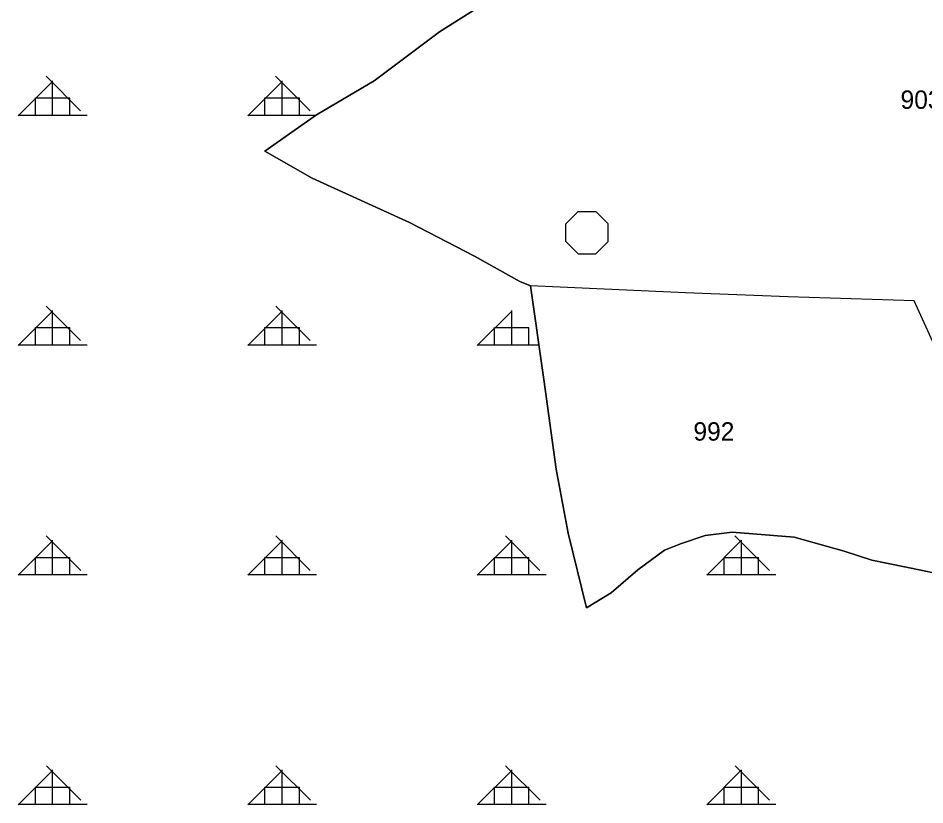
# Model space of a CAD drawing. Extents: x 410727 to 412947, y 4463506 to 4466382.
# Drawn here: x 411997.1 to 412194.6, y 4465173 to 4465344.2 of the extents above; entities that cross this region are included whole.
import ezdxf

# ---------------------------------------------------------------- set-up
doc = ezdxf.new("R2010")
doc.units = 0
for name, color, linetype in [('ADAKENARI', 7, 'Continuous'), ('KDS_PARSEL_NO', 7, 'Continuous'), ('KDS_PL', 7, 'Continuous'), ('PL_AYA_ORMAN', 7, 'Continuous'), ('PL_KA_TARIM_DIGER', 7, 'Continuous'), ('TR_ORMAN', 7, 'Continuous'), ('TR_TARIMALANI', 7, 'Continuous')]:
    doc.layers.add(name, color=color, linetype=linetype)

msp = doc.modelspace()

# ---------------------------------------------------------------- linework, layer by layer
at = {"layer": 'ADAKENARI'}
for p, q in [((412098.34, 4465347.2), (412088.91, 4465341.23)), ((412088.91, 4465341.23), (412074.64, 4465330.54)), ((412074.64, 4465330.54), (412062.11, 4465323.2)), ((412062.11, 4465323.2), (412050.82, 4465315.25)), ((412050.82, 4465315.25), (412061.12, 4465309.4)), ((412061.12, 4465309.4), (412082.33, 4465299.71)), ((412082.33, 4465299.71), (412096.48, 4465292.37)), ((412096.48, 4465292.37), (412106.4, 4465286.9)), ((412106.4, 4465286.9), (412108.68, 4465285.94)), ((412108.68, 4465285.94), (412111.63, 4465265.58)), ((412111.63, 4465265.58), (412114.28, 4465246.01)), ((412114.28, 4465246.01), (412116.93, 4465232.08)), ((412146.76, 4465231.62), (412152.64, 4465232.35)), ((412152.64, 4465232.35), (412166.15, 4465231.22)), ((412116.93, 4465232.08), (412120.9, 4465215.82)), ((412141.61, 4465229.85), (412146.76, 4465231.62)), ((412166.15, 4465231.22), (412177.01, 4465228.16)), ((412132.04, 4465224.13), (412137.91, 4465228.4)), ((412137.91, 4465228.4), (412141.61, 4465229.85)), ((412177.01, 4465228.16), (412183.05, 4465226.22)), ((412183.05, 4465226.22), (412194.07, 4465223.96)), ((412126.25, 4465219.13), (412132.04, 4465224.13)), ((412194.07, 4465223.96), (412202.76, 4465222.11)), ((412120.9, 4465215.82), (412126.25, 4465219.13))]:
    msp.add_line(p, q, dxfattribs=at)
at = {"layer": 'KDS_PL'}
for p, q in [((412088.91, 4465341.23), (412098.34, 4465347.2)), ((412074.64, 4465330.54), (412088.91, 4465341.23)), ((412062.11, 4465323.2), (412074.64, 4465330.54)), ((412050.82, 4465315.25), (412062.11, 4465323.2)), ((412061.12, 4465309.4), (412050.82, 4465315.25)), ((412082.33, 4465299.71), (412061.12, 4465309.4)), ((412096.48, 4465292.37), (412082.33, 4465299.71)), ((412106.4, 4465286.9), (412096.48, 4465292.37)), ((412108.68, 4465285.94), (412106.4, 4465286.9)), ((412142.42, 4465284.44), (412108.68, 4465285.94)), ((412108.68, 4465285.94), (412111.63, 4465265.58)), ((412164.81, 4465283.54), (412142.42, 4465284.44)), ((412192.28, 4465282.65), (412164.81, 4465283.54)), ((412197.06, 4465272.17), (412192.28, 4465282.65)), ((412111.63, 4465265.58), (412114.28, 4465246.01)), ((412114.28, 4465246.01), (412116.93, 4465232.08)), ((412146.76, 4465231.62), (412152.64, 4465232.35)), ((412152.64, 4465232.35), (412166.15, 4465231.22)), ((412116.93, 4465232.08), (412120.9, 4465215.82)), ((412141.61, 4465229.85), (412146.76, 4465231.62)), ((412166.15, 4465231.22), (412177.01, 4465228.16)), ((412132.04, 4465224.13), (412137.91, 4465228.4)), ((412137.91, 4465228.4), (412141.61, 4465229.85)), ((412177.01, 4465228.16), (412183.05, 4465226.22)), ((412183.05, 4465226.22), (412194.07, 4465223.96)), ((412126.25, 4465219.13), (412132.04, 4465224.13)), ((412194.07, 4465223.96), (412202.76, 4465222.11)), ((412120.9, 4465215.82), (412126.25, 4465219.13))]:
    msp.add_line(p, q, dxfattribs=at)
at = {"layer": 'PL_AYA_ORMAN'}
msp.add_lwpolyline([(412202.76, 4465222.11), (412194.07, 4465223.96), (412183.05, 4465226.22), (412177.01, 4465228.16), (412166.15, 4465231.22), (412152.64, 4465232.35), (412146.76, 4465231.62), (412141.61, 4465229.85), (412137.91, 4465228.4), (412132.04, 4465224.13), (412126.25, 4465219.13), (412120.9, 4465215.82), (412116.93, 4465232.08), (412114.28, 4465246.01), (412111.63, 4465265.58), (412108.68, 4465285.94), (412106.4, 4465286.9), (412096.48, 4465292.37), (412082.33, 4465299.71), (412061.12, 4465309.4), (412050.82, 4465315.25), (412062.11, 4465323.2), (412074.64, 4465330.54), (412088.91, 4465341.23), (412098.34, 4465347.2)], dxfattribs=at)
at = {"layer": 'PL_KA_TARIM_DIGER'}
msp.add_lwpolyline([(412202.76, 4465222.11), (412194.07, 4465223.96), (412183.05, 4465226.22), (412177.01, 4465228.16), (412166.15, 4465231.22), (412152.64, 4465232.35), (412146.76, 4465231.62), (412141.61, 4465229.85), (412137.91, 4465228.4), (412132.04, 4465224.13), (412126.25, 4465219.13), (412120.9, 4465215.82), (412116.93, 4465232.08), (412114.28, 4465246.01), (412111.63, 4465265.58), (412108.68, 4465285.94), (412106.4, 4465286.9), (412096.48, 4465292.37), (412082.33, 4465299.71), (412061.12, 4465309.4), (412050.82, 4465315.25), (412062.11, 4465323.2), (412074.64, 4465330.54), (412088.91, 4465341.23), (412098.34, 4465347.2)], dxfattribs=at)
at = {"layer": 'TR_ORMAN'}
for p, q in [((412010.69, 4465324.06), (412003.19, 4465331.56)), ((412010.69, 4465324.06), (412003.19, 4465331.56)), ((412010.69, 4465324.06), (412003.19, 4465331.56)), ((412010.69, 4465324.06), (412003.19, 4465331.56)), ((412060.68, 4465324.06), (412053.18, 4465331.56)), ((412060.68, 4465324.06), (412053.18, 4465331.56)), ((412060.68, 4465324.06), (412053.18, 4465331.56)), ((412060.68, 4465324.06), (412053.18, 4465331.56)), ((412060.68, 4465324.06), (412053.18, 4465331.56)), ((412060.68, 4465324.06), (412053.18, 4465331.56)), ((412060.68, 4465324.06), (412053.18, 4465331.56)), ((412060.68, 4465324.06), (412053.18, 4465331.56)), ((411997.11, 4465322.94), (412004.61, 4465330.44)), ((411997.11, 4465322.94), (412004.61, 4465330.44)), ((411997.11, 4465322.94), (412004.61, 4465330.44)), ((411997.11, 4465322.94), (412004.61, 4465330.44)), ((412004.62, 4465323.09), (412004.62, 4465330.59)), ((412004.62, 4465323.09), (412004.62, 4465330.59)), ((412004.62, 4465323.09), (412004.62, 4465330.59)), ((412004.62, 4465323.09), (412004.62, 4465330.59)), ((412047.11, 4465322.95), (412054.61, 4465330.45)), ((412047.11, 4465322.95), (412054.61, 4465330.45)), ((412047.11, 4465322.95), (412054.61, 4465330.45)), ((412047.11, 4465322.95), (412054.61, 4465330.45)), ((412054.62, 4465323.09), (412054.62, 4465330.59)), ((412054.62, 4465323.09), (412054.62, 4465330.59)), ((412054.62, 4465323.09), (412054.62, 4465330.59)), ((412054.62, 4465323.09), (412054.62, 4465330.59)), ((412000.87, 4465323.09), (412000.87, 4465326.84)), ((412000.87, 4465326.84), (412008.37, 4465326.84)), ((412000.87, 4465323.09), (412000.87, 4465326.84)), ((412000.87, 4465326.84), (412008.37, 4465326.84)), ((412000.87, 4465323.09), (412000.87, 4465326.84)), ((412000.87, 4465326.84), (412008.37, 4465326.84)), ((412000.87, 4465323.09), (412000.87, 4465326.84)), ((412000.87, 4465326.84), (412008.37, 4465326.84)), ((412008.37, 4465323.09), (412008.37, 4465326.84)), ((412008.37, 4465323.09), (412008.37, 4465326.84)), ((412008.37, 4465323.09), (412008.37, 4465326.84)), ((412008.37, 4465323.09), (412008.37, 4465326.84)), ((412050.87, 4465323.09), (412050.87, 4465326.84)), ((412050.87, 4465326.84), (412058.37, 4465326.84)), ((412050.87, 4465323.09), (412050.87, 4465326.84)), ((412050.87, 4465326.84), (412058.37, 4465326.84)), ((412050.87, 4465323.09), (412050.87, 4465326.84)), ((412050.87, 4465326.84), (412058.37, 4465326.84)), ((412050.87, 4465323.09), (412050.87, 4465326.84)), ((412050.87, 4465326.84), (412058.37, 4465326.84)), ((412058.37, 4465323.09), (412058.37, 4465326.84)), ((412058.37, 4465323.09), (412058.37, 4465326.84)), ((412058.37, 4465323.09), (412058.37, 4465326.84)), ((412058.37, 4465323.09), (412058.37, 4465326.84)), ((411997.12, 4465323.09), (412012.12, 4465323.09)), ((411997.12, 4465323.09), (412012.12, 4465323.09)), ((411997.12, 4465323.09), (412012.12, 4465323.09)), ((411997.12, 4465323.09), (412012.12, 4465323.09)), ((412047.12, 4465323.09), (412061.95, 4465323.09)), ((412047.12, 4465323.09), (412061.95, 4465323.09)), ((412047.12, 4465323.09), (412061.95, 4465323.09)), ((412047.12, 4465323.09), (412061.95, 4465323.09)), ((412010.72, 4465274.04), (412003.22, 4465281.54)), ((412010.72, 4465274.04), (412003.22, 4465281.54)), ((412010.72, 4465274.04), (412003.22, 4465281.54)), ((412010.72, 4465274.04), (412003.22, 4465281.54)), ((412060.71, 4465274.04), (412053.21, 4465281.54)), ((412060.71, 4465274.04), (412053.21, 4465281.54)), ((412060.71, 4465274.04), (412053.21, 4465281.54)), ((412060.71, 4465274.04), (412053.21, 4465281.54)), ((411997.11, 4465272.95), (412004.61, 4465280.45)), ((411997.11, 4465272.95), (412004.61, 4465280.45)), ((411997.11, 4465272.95), (412004.61, 4465280.45)), ((411997.11, 4465272.95), (412004.61, 4465280.45)), ((412004.62, 4465273.09), (412004.62, 4465280.59)), ((412004.62, 4465273.09), (412004.62, 4465280.59)), ((412004.62, 4465273.09), (412004.62, 4465280.59)), ((412004.62, 4465273.09), (412004.62, 4465280.59)), ((412047.11, 4465272.96), (412054.61, 4465280.46)), ((412047.11, 4465272.96), (412054.61, 4465280.46)), ((412047.11, 4465272.96), (412054.61, 4465280.46)), ((412047.11, 4465272.96), (412054.61, 4465280.46)), ((412054.62, 4465273.09), (412054.62, 4465280.59)), ((412054.62, 4465273.09), (412054.62, 4465280.59)), ((412054.62, 4465273.09), (412054.62, 4465280.59)), ((412054.62, 4465273.09), (412054.62, 4465280.59)), ((412097.11, 4465272.97), (412104.61, 4465280.46)), ((412097.11, 4465272.97), (412104.61, 4465280.46)), ((412097.11, 4465272.97), (412104.61, 4465280.46)), ((412097.11, 4465272.97), (412104.61, 4465280.46)), ((412104.62, 4465273.09), (412104.62, 4465280.59)), ((412104.62, 4465273.09), (412104.62, 4465280.59)), ((412104.62, 4465273.09), (412104.62, 4465280.59)), ((412104.62, 4465273.09), (412104.62, 4465280.59)), ((412000.87, 4465273.09), (412000.87, 4465276.84)), ((412000.87, 4465276.84), (412008.37, 4465276.84)), ((412000.87, 4465273.09), (412000.87, 4465276.84)), ((412000.87, 4465276.84), (412008.37, 4465276.84)), ((412000.87, 4465273.09), (412000.87, 4465276.84)), ((412000.87, 4465276.84), (412008.37, 4465276.84)), ((412000.87, 4465273.09), (412000.87, 4465276.84)), ((412000.87, 4465276.84), (412008.37, 4465276.84)), ((412008.37, 4465273.09), (412008.37, 4465276.84)), ((412008.37, 4465273.09), (412008.37, 4465276.84)), ((412008.37, 4465273.09), (412008.37, 4465276.84)), ((412008.37, 4465273.09), (412008.37, 4465276.84)), ((412050.87, 4465273.09), (412050.87, 4465276.84)), ((412050.87, 4465276.84), (412058.37, 4465276.84)), ((412050.87, 4465273.09), (412050.87, 4465276.84)), ((412050.87, 4465276.84), (412058.37, 4465276.84)), ((412050.87, 4465273.09), (412050.87, 4465276.84)), ((412050.87, 4465276.84), (412058.37, 4465276.84)), ((412050.87, 4465273.09), (412050.87, 4465276.84)), ((412050.87, 4465276.84), (412058.37, 4465276.84)), ((412058.37, 4465273.09), (412058.37, 4465276.84)), ((412058.37, 4465273.09), (412058.37, 4465276.84)), ((412058.37, 4465273.09), (412058.37, 4465276.84)), ((412058.37, 4465273.09), (412058.37, 4465276.84)), ((412100.87, 4465273.09), (412100.87, 4465276.84)), ((412100.87, 4465276.84), (412108.37, 4465276.84)), ((412100.87, 4465273.09), (412100.87, 4465276.84)), ((412100.87, 4465276.84), (412108.37, 4465276.84)), ((412100.87, 4465273.09), (412100.87, 4465276.84)), ((412100.87, 4465276.84), (412108.37, 4465276.84)), ((412100.87, 4465273.09), (412100.87, 4465276.84)), ((412100.87, 4465276.84), (412108.37, 4465276.84)), ((412108.37, 4465273.09), (412108.37, 4465276.84)), ((412108.37, 4465273.09), (412108.37, 4465276.84)), ((412108.37, 4465273.09), (412108.37, 4465276.84)), ((412108.37, 4465273.09), (412108.37, 4465276.84)), ((411997.12, 4465273.09), (412012.12, 4465273.09)), ((411997.12, 4465273.09), (412012.12, 4465273.09)), ((411997.12, 4465273.09), (412012.12, 4465273.09)), ((411997.12, 4465273.09), (412012.12, 4465273.09)), ((412047.12, 4465273.09), (412062.12, 4465273.09)), ((412047.12, 4465273.09), (412062.12, 4465273.09)), ((412047.12, 4465273.09), (412062.12, 4465273.09)), ((412047.12, 4465273.09), (412062.12, 4465273.09)), ((412097.12, 4465273.09), (412110.54, 4465273.09)), ((412097.12, 4465273.09), (412110.54, 4465273.09)), ((412097.12, 4465273.09), (412110.54, 4465273.09)), ((412097.12, 4465273.09), (412110.54, 4465273.09)), ((411997.11, 4465222.96), (412004.61, 4465230.46)), ((411997.11, 4465222.96), (412004.61, 4465230.46)), ((411997.11, 4465222.96), (412004.61, 4465230.46)), ((411997.11, 4465222.96), (412004.61, 4465230.46)), ((412010.75, 4465224.01), (412003.25, 4465231.51)), ((412010.75, 4465224.01), (412003.25, 4465231.51)), ((412010.75, 4465224.01), (412003.25, 4465231.51)), ((412010.75, 4465224.01), (412003.25, 4465231.51)), ((412004.62, 4465223.09), (412004.62, 4465230.59)), ((412004.62, 4465223.09), (412004.62, 4465230.59)), ((412004.62, 4465223.09), (412004.62, 4465230.59)), ((412004.62, 4465223.09), (412004.62, 4465230.59)), ((412047.11, 4465222.97), (412054.61, 4465230.46)), ((412047.11, 4465222.97), (412054.61, 4465230.46)), ((412047.11, 4465222.97), (412054.61, 4465230.46)), ((412047.11, 4465222.97), (412054.61, 4465230.46)), ((412060.74, 4465224.01), (412053.24, 4465231.51)), ((412060.74, 4465224.01), (412053.24, 4465231.51)), ((412060.74, 4465224.01), (412053.24, 4465231.51)), ((412060.74, 4465224.01), (412053.24, 4465231.51)), ((412054.62, 4465223.09), (412054.62, 4465230.59)), ((412054.62, 4465223.09), (412054.62, 4465230.59)), ((412054.62, 4465223.09), (412054.62, 4465230.59)), ((412054.62, 4465223.09), (412054.62, 4465230.59)), ((412097.11, 4465222.97), (412104.61, 4465230.47)), ((412097.11, 4465222.97), (412104.61, 4465230.47)), ((412097.11, 4465222.97), (412104.61, 4465230.47)), ((412097.11, 4465222.97), (412104.61, 4465230.47)), ((412110.73, 4465224.01), (412103.23, 4465231.51)), ((412110.73, 4465224.01), (412103.23, 4465231.51)), ((412110.73, 4465224.01), (412103.23, 4465231.51)), ((412110.73, 4465224.01), (412103.23, 4465231.51)), ((412104.62, 4465223.09), (412104.62, 4465230.59)), ((412104.62, 4465223.09), (412104.62, 4465230.59)), ((412104.62, 4465223.09), (412104.62, 4465230.59)), ((412104.62, 4465223.09), (412104.62, 4465230.59)), ((412147.11, 4465222.98), (412154.61, 4465230.48)), ((412147.11, 4465222.98), (412154.61, 4465230.48)), ((412147.11, 4465222.98), (412154.61, 4465230.48)), ((412147.11, 4465222.98), (412154.61, 4465230.48)), ((412160.73, 4465224.01), (412153.23, 4465231.51)), ((412160.73, 4465224.01), (412153.23, 4465231.51)), ((412160.73, 4465224.01), (412153.23, 4465231.51)), ((412160.73, 4465224.01), (412153.23, 4465231.51)), ((412154.62, 4465223.09), (412154.62, 4465230.59)), ((412154.62, 4465223.09), (412154.62, 4465230.59)), ((412154.62, 4465223.09), (412154.62, 4465230.59)), ((412154.62, 4465223.09), (412154.62, 4465230.59)), ((412000.87, 4465223.09), (412000.87, 4465226.84)), ((412000.87, 4465226.84), (412008.37, 4465226.84)), ((412000.87, 4465223.09), (412000.87, 4465226.84)), ((412000.87, 4465226.84), (412008.37, 4465226.84)), ((412000.87, 4465223.09), (412000.87, 4465226.84)), ((412000.87, 4465226.84), (412008.37, 4465226.84)), ((412000.87, 4465223.09), (412000.87, 4465226.84)), ((412000.87, 4465226.84), (412008.37, 4465226.84)), ((412008.37, 4465223.09), (412008.37, 4465226.84)), ((412008.37, 4465223.09), (412008.37, 4465226.84)), ((412008.37, 4465223.09), (412008.37, 4465226.84)), ((412008.37, 4465223.09), (412008.37, 4465226.84)), ((412050.87, 4465223.09), (412050.87, 4465226.84)), ((412050.87, 4465226.84), (412058.37, 4465226.84)), ((412050.87, 4465223.09), (412050.87, 4465226.84)), ((412050.87, 4465226.84), (412058.37, 4465226.84)), ((412050.87, 4465223.09), (412050.87, 4465226.84)), ((412050.87, 4465226.84), (412058.37, 4465226.84)), ((412050.87, 4465223.09), (412050.87, 4465226.84)), ((412050.87, 4465226.84), (412058.37, 4465226.84)), ((412058.37, 4465223.09), (412058.37, 4465226.84)), ((412058.37, 4465223.09), (412058.37, 4465226.84)), ((412058.37, 4465223.09), (412058.37, 4465226.84)), ((412058.37, 4465223.09), (412058.37, 4465226.84)), ((412100.87, 4465223.09), (412100.87, 4465226.84)), ((412100.87, 4465226.84), (412108.37, 4465226.84)), ((412100.87, 4465223.09), (412100.87, 4465226.84)), ((412100.87, 4465226.84), (412108.37, 4465226.84)), ((412100.87, 4465223.09), (412100.87, 4465226.84)), ((412100.87, 4465226.84), (412108.37, 4465226.84)), ((412100.87, 4465223.09), (412100.87, 4465226.84)), ((412100.87, 4465226.84), (412108.37, 4465226.84)), ((412108.37, 4465223.09), (412108.37, 4465226.84)), ((412108.37, 4465223.09), (412108.37, 4465226.84)), ((412108.37, 4465223.09), (412108.37, 4465226.84)), ((412108.37, 4465223.09), (412108.37, 4465226.84)), ((412150.87, 4465223.09), (412150.87, 4465226.84)), ((412150.87, 4465226.84), (412158.37, 4465226.84)), ((412150.87, 4465223.09), (412150.87, 4465226.84)), ((412150.87, 4465226.84), (412158.37, 4465226.84)), ((412150.87, 4465223.09), (412150.87, 4465226.84)), ((412150.87, 4465226.84), (412158.37, 4465226.84)), ((412150.87, 4465223.09), (412150.87, 4465226.84)), ((412150.87, 4465226.84), (412158.37, 4465226.84)), ((412158.37, 4465223.09), (412158.37, 4465226.84)), ((412158.37, 4465223.09), (412158.37, 4465226.84)), ((412158.37, 4465223.09), (412158.37, 4465226.84)), ((412158.37, 4465223.09), (412158.37, 4465226.84)), ((411997.12, 4465223.09), (412012.12, 4465223.09)), ((411997.12, 4465223.09), (412012.12, 4465223.09)), ((411997.12, 4465223.09), (412012.12, 4465223.09)), ((411997.12, 4465223.09), (412012.12, 4465223.09)), ((412047.12, 4465223.09), (412062.12, 4465223.09)), ((412047.12, 4465223.09), (412062.12, 4465223.09)), ((412047.12, 4465223.09), (412062.12, 4465223.09)), ((412047.12, 4465223.09), (412062.12, 4465223.09)), ((412097.12, 4465223.09), (412112.12, 4465223.09)), ((412097.12, 4465223.09), (412112.12, 4465223.09)), ((412097.12, 4465223.09), (412112.12, 4465223.09)), ((412097.12, 4465223.09), (412112.12, 4465223.09)), ((412147.12, 4465223.09), (412162.12, 4465223.09)), ((412147.12, 4465223.09), (412162.12, 4465223.09)), ((412147.12, 4465223.09), (412162.12, 4465223.09)), ((412147.12, 4465223.09), (412162.12, 4465223.09)), ((412010.78, 4465173.99), (412003.28, 4465181.49)), ((412010.78, 4465173.99), (412003.28, 4465181.49)), ((412010.78, 4465173.99), (412003.28, 4465181.49)), ((412010.78, 4465173.99), (412003.28, 4465181.49)), ((412060.77, 4465173.99), (412053.27, 4465181.49)), ((412060.77, 4465173.99), (412053.27, 4465181.49)), ((412060.77, 4465173.99), (412053.27, 4465181.49)), ((412060.77, 4465173.99), (412053.27, 4465181.49)), ((412110.77, 4465173.99), (412103.27, 4465181.49)), ((412110.77, 4465173.99), (412103.27, 4465181.49)), ((412110.77, 4465173.99), (412103.27, 4465181.49)), ((412110.77, 4465173.99), (412103.27, 4465181.49)), ((412160.76, 4465173.99), (412153.26, 4465181.49)), ((412160.76, 4465173.99), (412153.26, 4465181.49)), ((412160.76, 4465173.99), (412153.26, 4465181.49)), ((412160.76, 4465173.99), (412153.26, 4465181.49)), ((411997.11, 4465172.97), (412004.61, 4465180.47)), ((411997.11, 4465172.97), (412004.61, 4465180.47)), ((411997.11, 4465172.97), (412004.61, 4465180.47)), ((411997.11, 4465172.97), (412004.61, 4465180.47)), ((412004.62, 4465173.09), (412004.62, 4465180.59)), ((412004.62, 4465173.09), (412004.62, 4465180.59)), ((412004.62, 4465173.09), (412004.62, 4465180.59)), ((412004.62, 4465173.09), (412004.62, 4465180.59)), ((412047.11, 4465172.97), (412054.61, 4465180.47)), ((412047.11, 4465172.97), (412054.61, 4465180.47)), ((412047.11, 4465172.97), (412054.61, 4465180.47)), ((412047.11, 4465172.97), (412054.61, 4465180.47)), ((412054.62, 4465173.09), (412054.62, 4465180.59)), ((412054.62, 4465173.09), (412054.62, 4465180.59)), ((412054.62, 4465173.09), (412054.62, 4465180.59)), ((412054.62, 4465173.09), (412054.62, 4465180.59)), ((412097.11, 4465172.98), (412104.61, 4465180.48)), ((412097.11, 4465172.98), (412104.61, 4465180.48)), ((412097.11, 4465172.98), (412104.61, 4465180.48)), ((412097.11, 4465172.98), (412104.61, 4465180.48)), ((412104.62, 4465173.09), (412104.62, 4465180.59)), ((412104.62, 4465173.09), (412104.62, 4465180.59)), ((412104.62, 4465173.09), (412104.62, 4465180.59)), ((412104.62, 4465173.09), (412104.62, 4465180.59)), ((412147.11, 4465172.99), (412154.61, 4465180.49)), ((412147.11, 4465172.99), (412154.61, 4465180.49)), ((412147.11, 4465172.99), (412154.61, 4465180.49)), ((412147.11, 4465172.99), (412154.61, 4465180.49)), ((412154.62, 4465173.09), (412154.62, 4465180.59)), ((412154.62, 4465173.09), (412154.62, 4465180.59)), ((412154.62, 4465173.09), (412154.62, 4465180.59)), ((412154.62, 4465173.09), (412154.62, 4465180.59)), ((412000.87, 4465173.09), (412000.87, 4465176.84)), ((412000.87, 4465176.84), (412008.37, 4465176.84)), ((412000.87, 4465173.09), (412000.87, 4465176.84)), ((412000.87, 4465176.84), (412008.37, 4465176.84)), ((412000.87, 4465173.09), (412000.87, 4465176.84)), ((412000.87, 4465176.84), (412008.37, 4465176.84)), ((412000.87, 4465173.09), (412000.87, 4465176.84)), ((412000.87, 4465176.84), (412008.37, 4465176.84)), ((412008.37, 4465173.09), (412008.37, 4465176.84)), ((412008.37, 4465173.09), (412008.37, 4465176.84)), ((412008.37, 4465173.09), (412008.37, 4465176.84)), ((412008.37, 4465173.09), (412008.37, 4465176.84)), ((412050.87, 4465173.09), (412050.87, 4465176.84)), ((412050.87, 4465176.84), (412058.37, 4465176.84)), ((412050.87, 4465173.09), (412050.87, 4465176.84)), ((412050.87, 4465176.84), (412058.37, 4465176.84)), ((412050.87, 4465173.09), (412050.87, 4465176.84)), ((412050.87, 4465176.84), (412058.37, 4465176.84)), ((412050.87, 4465173.09), (412050.87, 4465176.84)), ((412050.87, 4465176.84), (412058.37, 4465176.84)), ((412058.37, 4465173.09), (412058.37, 4465176.84)), ((412058.37, 4465173.09), (412058.37, 4465176.84)), ((412058.37, 4465173.09), (412058.37, 4465176.84)), ((412058.37, 4465173.09), (412058.37, 4465176.84)), ((412100.87, 4465173.09), (412100.87, 4465176.84)), ((412100.87, 4465176.84), (412108.37, 4465176.84)), ((412100.87, 4465173.09), (412100.87, 4465176.84)), ((412100.87, 4465176.84), (412108.37, 4465176.84)), ((412100.87, 4465173.09), (412100.87, 4465176.84)), ((412100.87, 4465176.84), (412108.37, 4465176.84)), ((412100.87, 4465173.09), (412100.87, 4465176.84)), ((412100.87, 4465176.84), (412108.37, 4465176.84)), ((412108.37, 4465173.09), (412108.37, 4465176.84)), ((412108.37, 4465173.09), (412108.37, 4465176.84)), ((412108.37, 4465173.09), (412108.37, 4465176.84)), ((412108.37, 4465173.09), (412108.37, 4465176.84)), ((412150.87, 4465176.84), (412158.37, 4465176.84)), ((412150.87, 4465173.09), (412150.87, 4465176.84)), ((412150.87, 4465176.84), (412158.37, 4465176.84)), ((412150.87, 4465173.09), (412150.87, 4465176.84)), ((412150.87, 4465176.84), (412158.37, 4465176.84)), ((412150.87, 4465173.09), (412150.87, 4465176.84)), ((412150.87, 4465176.84), (412158.37, 4465176.84)), ((412150.87, 4465173.09), (412150.87, 4465176.84)), ((412158.37, 4465173.09), (412158.37, 4465176.84)), ((412158.37, 4465173.09), (412158.37, 4465176.84)), ((412158.37, 4465173.09), (412158.37, 4465176.84)), ((412158.37, 4465173.09), (412158.37, 4465176.84)), ((411997.12, 4465173.09), (412012.12, 4465173.09)), ((411997.12, 4465173.09), (412012.12, 4465173.09)), ((411997.12, 4465173.09), (412012.12, 4465173.09)), ((411997.12, 4465173.09), (412012.12, 4465173.09)), ((412047.12, 4465173.09), (412062.12, 4465173.09)), ((412047.12, 4465173.09), (412062.12, 4465173.09)), ((412047.12, 4465173.09), (412062.12, 4465173.09)), ((412047.12, 4465173.09), (412062.12, 4465173.09)), ((412097.12, 4465173.09), (412112.12, 4465173.09)), ((412097.12, 4465173.09), (412112.12, 4465173.09)), ((412097.12, 4465173.09), (412112.12, 4465173.09)), ((412097.12, 4465173.09), (412112.12, 4465173.09)), ((412147.12, 4465173.09), (412162.12, 4465173.09)), ((412147.12, 4465173.09), (412162.12, 4465173.09)), ((412147.12, 4465173.09), (412162.12, 4465173.09)), ((412147.12, 4465173.09), (412162.12, 4465173.09))]:
    msp.add_line(p, q, dxfattribs=at)
at = {"layer": 'TR_TARIMALANI'}
for p, q in [((412116.37, 4465299.43), (412119.08, 4465302.14)), ((412116.37, 4465299.43), (412119.08, 4465302.14)), ((412119.08, 4465302.14), (412122.91, 4465302.14)), ((412119.08, 4465302.14), (412122.91, 4465302.14)), ((412125.62, 4465299.43), (412122.91, 4465302.14)), ((412125.62, 4465299.43), (412122.91, 4465302.14)), ((412116.37, 4465295.6), (412116.37, 4465299.43)), ((412116.37, 4465295.6), (412116.37, 4465299.43)), ((412125.62, 4465295.6), (412125.62, 4465299.43)), ((412125.62, 4465295.6), (412125.62, 4465299.43)), ((412119.08, 4465292.89), (412116.37, 4465295.6)), ((412119.08, 4465292.89), (412116.37, 4465295.6)), ((412122.91, 4465292.89), (412125.62, 4465295.6)), ((412122.91, 4465292.89), (412125.62, 4465295.6)), ((412119.08, 4465292.89), (412122.91, 4465292.89)), ((412119.08, 4465292.89), (412122.91, 4465292.89))]:
    msp.add_line(p, q, dxfattribs=at)

# ---------------------------------------------------------------- texts
at = {"layer": 'KDS_PARSEL_NO'}
for s, p in [('903', (412189.29, 4465324.47)), ('992', (412144.18, 4465252.25))]:
    msp.add_text(s, height=4, dxfattribs=at).set_placement(p)

doc.saveas('drawing.dxf')
